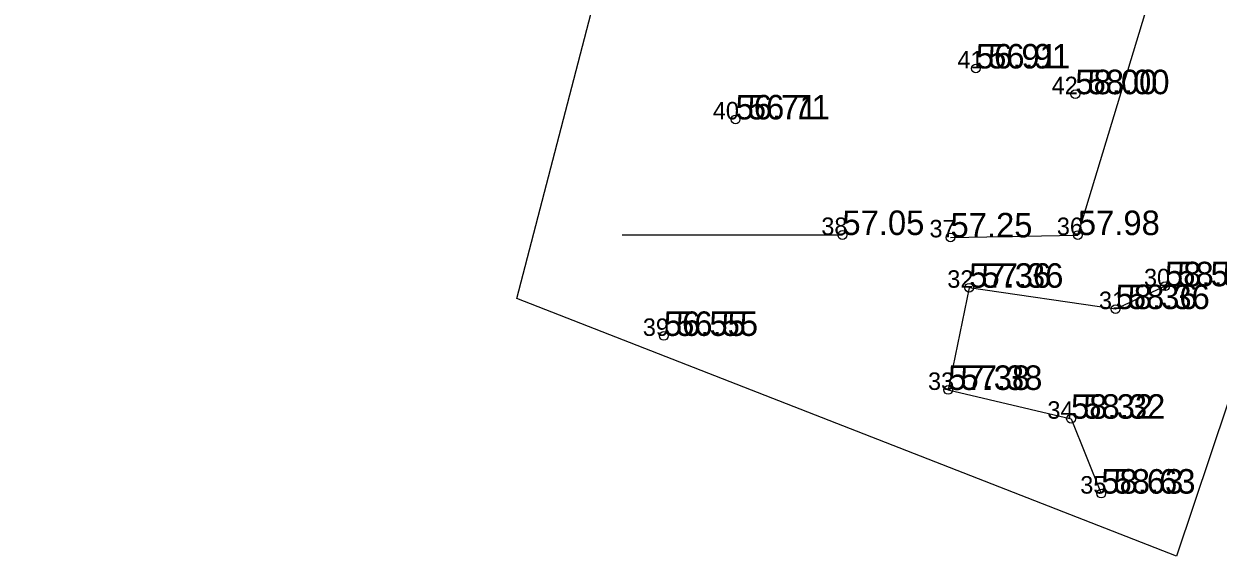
# Model space of a CAD drawing. Extents: x 554846 to 556995, y 6445875 to 6446723.
# Drawn here: x 556006.58 to 556040.69, y 6446042.53 to 6446057.74 of the extents above; entities that cross this region are included whole.
import ezdxf

# ---------------------------------------------------------------- set-up
doc = ezdxf.new("R2010")
doc.units = 0
for name, color, linetype in [('AED', 7, 'Continuous'), ('KORGUS-EH2000', 7, 'Continuous'), ('MOOTKORG-EH2000', 7, 'Continuous'), ('MOOTMPUNKT', 7, 'Continuous'), ('MOOTNR', 7, 'Continuous'), ('MOOTPIIR', 7, 'Continuous'), ('TEE', 7, 'Continuous')]:
    doc.layers.add(name, color=color, linetype=linetype)

msp = doc.modelspace()

# ---------------------------------------------------------------- linework, layer by layer
at = {"layer": 'AED'}
for points in [[(556033.049, 6446051.64), (556036.688, 6446051.706), (556063.341, 6446139.502), (556071.485, 6446165.879), (556080.793, 6446177.291), (556081.44, 6446177.495)], [(556029.96, 6446051.708), (556023.673, 6446051.708)]]:
    msp.add_lwpolyline(points, dxfattribs=at)
at = {"layer": 'KORGUS-EH2000'}
for centre in [(556033.774, 6446056.465), (556036.615, 6446055.73), (556026.909, 6446055.01), (556033.583, 6446050.201), (556039.178, 6446050.243), (556037.766, 6446049.591), (556024.86, 6446048.825), (556032.983, 6446047.282), (556036.493, 6446046.459), (556037.357, 6446044.32)]:
    msp.add_circle(centre, 0.125, dxfattribs=at)
at = {"layer": 'MOOTMPUNKT'}
for centre in [(556033.774, 6446056.465), (556036.615, 6446055.73), (556026.909, 6446055.01), (556029.96, 6446051.708), (556033.049, 6446051.64), (556036.688, 6446051.706), (556033.583, 6446050.201), (556039.178, 6446050.243), (556037.766, 6446049.591), (556024.86, 6446048.825), (556032.983, 6446047.282), (556036.493, 6446046.459), (556037.357, 6446044.32)]:
    msp.add_circle(centre, 0.125, dxfattribs=at)
at = {"layer": 'MOOTPIIR'}
msp.add_lwpolyline([(555725.406, 6446281.484), (555817.048, 6446350.749), (555844.86, 6446384.534), (555860.36, 6446384.318), (555887.486, 6446366.763), (555962.357, 6446288.251), (556053.206, 6446282.949), (556087.085, 6446184.663), (556039.505, 6446042.535), (556020.655, 6446049.893), (556035.735, 6446107.711), (556060, 6446188.14), (556037.913, 6446255.097), (555953.523, 6446260.374), (555856.555, 6446356.048), (555752.836, 6446263.064)], dxfattribs=at)
at = {"layer": 'TEE'}
msp.add_lwpolyline([(556039.178, 6446050.243), (556037.766, 6446049.591), (556033.583, 6446050.201), (556032.983, 6446047.282), (556036.493, 6446046.459), (556037.357, 6446044.32)], dxfattribs=at)

# ---------------------------------------------------------------- texts
at = {"layer": 'KORGUS-EH2000'}
for s, p in [('56.91', (556034.124, 6446056.465)), ('58.00', (556036.965, 6446055.73)), ('56.71', (556027.259, 6446055.01)), ('57.36', (556033.933, 6446050.201)), ('58.52', (556039.528, 6446050.243)), ('58.36', (556038.116, 6446049.591)), ('56.55', (556025.21, 6446048.825)), ('57.38', (556033.333, 6446047.282)), ('58.32', (556036.843, 6446046.459)), ('58.63', (556037.707, 6446044.32))]:
    msp.add_text(s, height=0.7, dxfattribs=at).set_placement(p)
at = {"layer": 'MOOTKORG-EH2000'}
for s, p in [('56.91', (556033.774, 6446056.465)), ('58.00', (556036.615, 6446055.73)), ('56.71', (556026.909, 6446055.01)), ('57.05', (556029.96, 6446051.708)), ('57.25', (556033.049, 6446051.64)), ('57.98', (556036.688, 6446051.706)), ('57.36', (556033.583, 6446050.201)), ('58.52', (556039.178, 6446050.243)), ('58.36', (556037.766, 6446049.591)), ('56.55', (556024.86, 6446048.825)), ('57.38', (556032.983, 6446047.282)), ('58.32', (556036.493, 6446046.459)), ('58.63', (556037.357, 6446044.32))]:
    msp.add_text(s, height=0.7, dxfattribs=at).set_placement(p)
at = {"layer": 'MOOTNR'}
for s, p in [('41', (556033.249, 6446056.465)), ('42', (556035.94, 6446055.73)), ('40', (556026.259, 6446055.01)), ('38', (556029.36, 6446051.708)), ('36', (556036.088, 6446051.706)), ('37', (556032.449, 6446051.64)), ('32', (556032.958, 6446050.201)), ('30', (556038.578, 6446050.243)), ('31', (556037.291, 6446049.591)), ('39', (556024.26, 6446048.825)), ('33', (556032.408, 6446047.282)), ('34', (556035.818, 6446046.459)), ('35', (556036.757, 6446044.32))]:
    msp.add_text(s, height=0.5, dxfattribs=at).set_placement(p)

doc.saveas('drawing.dxf')
